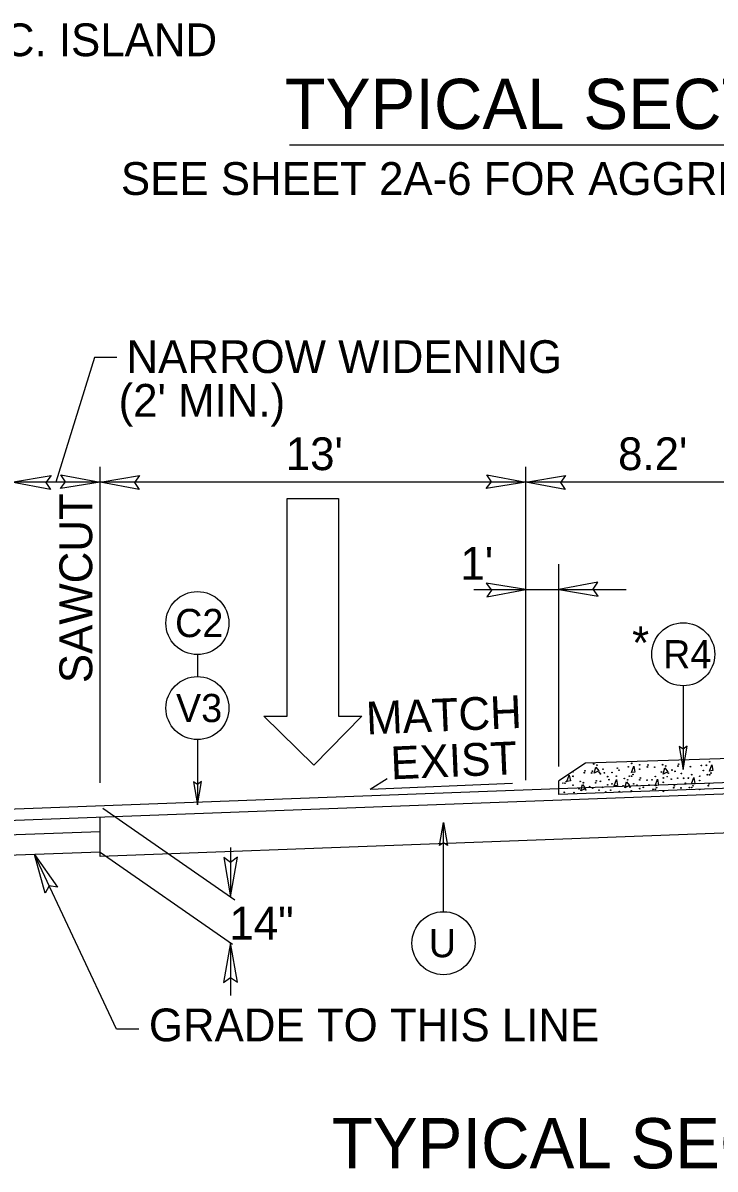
# Model space of a CAD drawing. Extents: x 573748 to 574632, y -54663 to -53209.
# Drawn here: x 574059.1 to 574090.8, y -53553.4 to -53500.9 of the extents above; entities that cross this region are included whole.
import ezdxf

# ---------------------------------------------------------------- set-up
doc = ezdxf.new("R2010")
doc.units = 0
for name, color, linetype in [('Prop Dimension', 7, 'Continuous'), ('Prop Dimension Text', 7, 'Continuous'), ('Prop Lane Arrow CELL', 7, 'Continuous'), ('Prop Terminator CELL', 7, 'Continuous'), ('Typical Arrow Superelevation CELL', 7, 'Continuous'), ('Typical Curb CELL', 7, 'Continuous'), ('Typical ID Circle CELL', 7, 'Continuous'), ('Typical Pavement Slope CELL', 7, 'Continuous'), ('Typical Terminator CELL', 7, 'Continuous'), ('Typical Text General CELL', 7, 'Continuous'), ('Typical Text ID Circle CELL', 7, 'Continuous'), ('Typical Text Label CELL', 7, 'Continuous')]:
    doc.layers.add(name, color=color, linetype=linetype)

msp = doc.modelspace()

# ---------------------------------------------------------------- linework, layer by layer
at = {"layer": 'Prop Dimension'}
for p, q in [((574062.619, -53535.664), (574062.619, -53521.214)), ((574082.119, -53535.548), (574082.119, -53521.214)), ((574062.619, -53521.907), (574058.56, -53521.907)), ((574082.119, -53521.907), (574062.619, -53521.907)), ((574094.001, -53521.907), (574082.119, -53521.907)), ((574083.619, -53534.926), (574083.619, -53525.657)), ((574079.741, -53526.824), (574086.705, -53526.824)), ((574084.854, -53534.767), (574083.619, -53535.575)), ((574094.001, -53534.479), (574084.854, -53534.767)), ((574094.001, -53535.561), (574083.619, -53535.949)), ((574083.619, -53536.206), (574083.619, -53535.575)), ((574094.001, -53535.818), (574083.619, -53536.206)), ((574062.752, -53536.827), (574068.787, -53541.022)), ((574094.001, -53537.874), (574062.619, -53539.048)), ((574062.619, -53538.84), (574068.684, -53543.056)), ((574062.619, -53539.048), (574062.619, -53538.84)), ((574068.598, -53538.637), (574068.598, -53540.89)), ((574068.598, -53542.996), (574068.598, -53545.398))]:
    msp.add_line(p, q, dxfattribs=at)
for points in [[(574063.388, -53516.206), (574062.367, -53516.206), (574060.59, -53521.907)], [(574064.398, -53546.943), (574063.377, -53546.943), (574059.618, -53538.952)]]:
    msp.add_lwpolyline(points, dxfattribs=at)
at = {"layer": 'Prop Lane Arrow CELL'}
for p, q in [((574071.193, -53532.624), (574071.193, -53522.649)), ((574071.193, -53522.649), (574073.545, -53522.649)), ((574073.545, -53522.649), (574073.545, -53532.624)), ((574072.405, -53534.869), (574070.125, -53532.624)), ((574070.125, -53532.624), (574071.193, -53532.624)), ((574074.613, -53532.624), (574072.405, -53534.869)), ((574073.545, -53532.624), (574074.613, -53532.624))]:
    msp.add_line(p, q, dxfattribs=at)
at = {"layer": 'Prop Terminator CELL'}
for points in [[(574060.357, -53522.24), (574058.56, -53521.907), (574060.375, -53521.61), (574060.141, -53521.927)], [(574060.822, -53521.574), (574062.619, -53521.907), (574060.804, -53522.204), (574061.039, -53521.886)], [(574064.415, -53522.24), (574062.619, -53521.907), (574064.433, -53521.61), (574064.199, -53521.927)], [(574080.322, -53521.574), (574082.119, -53521.907), (574080.304, -53522.204), (574080.539, -53521.886)], [(574083.915, -53522.24), (574082.119, -53521.907), (574083.933, -53521.61), (574083.699, -53521.927)], [(574080.322, -53527.158), (574082.119, -53526.824), (574080.304, -53526.528), (574080.539, -53526.845)], [(574085.415, -53526.491), (574083.619, -53526.824), (574085.433, -53527.121), (574085.199, -53526.804)], [(574060.104, -53540.714), (574059.618, -53538.952), (574060.678, -53540.454), (574060.291, -53540.383)], [(574068.288, -53539.09), (574068.598, -53540.89), (574068.918, -53539.08), (574068.598, -53539.31)], [(574068.908, -53544.796), (574068.598, -53542.996), (574068.278, -53544.806), (574068.598, -53544.576)]]:
    msp.add_lwpolyline(points, close=True, dxfattribs=at)
at = {"layer": 'Typical Arrow Superelevation CELL'}
for q in [(574075.763, -53535.47), (574081.509, -53535.682)]:
    msp.add_line((574074.991, -53535.961), q, dxfattribs=at)
at = {"layer": 'Typical Curb CELL'}
for p, q in [((574085.248, -53535.231), (574085.325, -53534.952)), ((574085.325, -53534.952), (574085.459, -53535.125)), ((574086.947, -53535.202), (574087.054, -53534.909)), ((574087.054, -53534.909), (574087.101, -53535.179)), ((574090.519, -53535.135), (574090.626, -53534.842)), ((574090.626, -53534.842), (574090.673, -53535.112)), ((574083.999, -53535.608), (574084.106, -53535.315)), ((574084.106, -53535.315), (574084.153, -53535.585)), ((574085.459, -53535.125), (574085.248, -53535.231)), ((574087.101, -53535.179), (574086.947, -53535.202)), ((574088.401, -53535.268), (574088.478, -53534.989)), ((574088.612, -53535.162), (574088.401, -53535.268)), ((574088.478, -53534.989), (574088.612, -53535.162)), ((574089.697, -53535.718), (574089.805, -53535.425)), ((574089.805, -53535.425), (574089.852, -53535.696)), ((574090.673, -53535.112), (574090.519, -53535.135)), ((574084.153, -53535.585), (574083.999, -53535.608)), ((574084.629, -53536.033), (574084.706, -53535.754)), ((574084.84, -53535.927), (574084.629, -53536.033)), ((574084.706, -53535.754), (574084.84, -53535.927)), ((574086.153, -53535.815), (574086.26, -53535.522)), ((574086.307, -53535.792), (574086.153, -53535.815)), ((574086.26, -53535.522), (574086.307, -53535.792)), ((574086.652, -53535.902), (574086.729, -53535.623)), ((574086.863, -53535.796), (574086.652, -53535.902)), ((574086.729, -53535.623), (574086.863, -53535.796)), ((574088.031, -53535.803), (574088.139, -53535.51)), ((574088.186, -53535.78), (574088.031, -53535.803)), ((574088.139, -53535.51), (574088.186, -53535.78)), ((574089.852, -53535.696), (574089.697, -53535.718))]:
    msp.add_line(p, q, dxfattribs=at)
for centre in [(574085.222, -53534.805), (574085.368, -53534.864), (574086.81, -53534.935), (574086.963, -53534.78), (574087.33, -53534.846), (574087.681, -53534.943), (574087.709, -53534.855), (574088.018, -53534.953), (574088.375, -53534.842), (574088.522, -53534.9), (574089.081, -53534.903), (574089.109, -53534.816), (574089.316, -53534.92), (574089.344, -53534.832), (574089.653, -53534.93), (574090.156, -53534.879), (574090.382, -53534.868), (574090.535, -53534.713), (574084.274, -53535.37), (574084.282, -53535.167), (574084.791, -53535.209), (574084.82, -53535.121), (574085.129, -53535.218), (574085.165, -53535.139), (574085.479, -53535.193), (574085.531, -53535.254), (574085.651, -53535.048), (574085.715, -53535.212), (574085.858, -53535.386), (574086.056, -53535.195), (574086.258, -53535.366), (574086.307, -53534.996), (574086.376, -53535.094), (574086.626, -53535.476), (574086.857, -53535.367), (574086.954, -53535.367), (574087.017, -53535.291), (574087.323, -53535.048), (574087.36, -53535.45), (574088.048, -53535.381), (574088.319, -53535.175), (574088.415, -53535.446), (574088.633, -53535.229), (574088.804, -53535.085), (574088.951, -53535.144), (574089.062, -53535.458), (574089.241, -53535.24), (574089.335, -53535.463), (574089.56, -53535.452), (574089.714, -53535.297), (574090.081, -53535.362), (574090.237, -53535.104), (574090.429, -53535.3), (574090.526, -53535.3), (574090.589, -53535.223), (574083.809, -53535.689), (574083.905, -53535.689), (574083.969, -53535.612), (574084.279, -53535.779), (574084.547, -53535.94), (574084.603, -53535.607), (574084.75, -53535.665), (574084.861, -53535.994), (574085.032, -53535.85), (574085.179, -53535.909), (574085.309, -53535.668), (574085.337, -53535.581), (574085.469, -53536.005), (574085.527, -53535.601), (574085.619, -53535.874), (574085.862, -53535.764), (574085.919, -53535.525), (574086.003, -53536.007), (574086.055, -53535.713), (574086.57, -53535.81), (574086.773, -53535.535), (574086.884, -53535.864), (574087.055, -53535.719), (574087.202, -53535.778), (574087.332, -53535.537), (574087.333, -53535.936), (574087.492, -53535.874), (574087.669, -53535.547), (574087.75, -53535.772), (574087.895, -53535.536), (574087.942, -53535.968), (574088.039, -53535.968), (574088.102, -53535.892), (574088.408, -53535.649), (574088.771, -53535.505), (574088.886, -53535.895), (574088.914, -53535.808), (574089.224, -53535.905), (574089.416, -53535.688), (574089.608, -53535.884), (574089.704, -53535.884), (574089.768, -53535.807), (574090.073, -53535.565), (574090.078, -53535.975), (574090.467, -53535.803), (574090.496, -53535.716), (574083.875, -53536.105), (574084.319, -53536.114), (574085.775, -53536.093), (574086.392, -53536.064), (574086.948, -53536.042), (574088.412, -53536.059)]:
    msp.add_ellipse(centre, major_axis=(0.0001, 0.0192), ratio=0.533333, dxfattribs=at)
msp.add_ellipse((574088.585, -53535.41), major_axis=(-0.0001, -0.0219), ratio=0.533333, start_param=2.050606, end_param=4.270718, dxfattribs=at)
at = {"layer": 'Typical ID Circle CELL'}
for p, q in [((574067.078, -53529.801), (574067.078, -53530.806)), ((574089.322, -53531.23), (574089.322, -53535.056)), ((574067.078, -53533.691), (574067.078, -53536.677)), ((574078.345, -53541.569), (574078.345, -53537.486))]:
    msp.add_line(p, q, dxfattribs=at)
for centre in [(574067.078, -53528.358), (574089.322, -53529.787), (574067.078, -53532.248), (574078.345, -53543.012)]:
    msp.add_circle(centre, 1.443, dxfattribs=at)
at = {"layer": 'Typical Pavement Slope CELL'}
for p, q in [((574083.619, -53535.949), (574052.56, -53537.111)), ((574094.001, -53536.075), (574052.064, -53537.644)), ((574062.619, -53538.84), (574062.619, -53537.249)), ((574062.619, -53537.909), (574051.426, -53538.328)), ((574062.619, -53538.84), (574050.528, -53539.292))]:
    msp.add_line(p, q, dxfattribs=at)
at = {"layer": 'Typical Terminator CELL'}
for points in [[(574089.14, -53534.002), (574089.322, -53535.056), (574089.509, -53533.996), (574089.322, -53534.131)], [(574066.896, -53535.623), (574067.078, -53536.677), (574067.265, -53535.617), (574067.078, -53535.752)], [(574078.163, -53538.541), (574078.345, -53537.486), (574078.532, -53538.546), (574078.345, -53538.412)]]:
    msp.add_lwpolyline(points, close=True, dxfattribs=at)
at = {"layer": 'Typical Text Label CELL'}
msp.add_line((574071.293, -53506.466), (574107.5, -53506.466), dxfattribs=at)

# ---------------------------------------------------------------- texts
at = {"layer": 'Prop Dimension'}
msp.add_text('GRADE TO THIS LINE', height=1.5, rotation=360, dxfattribs=at).set_placement((574064.857, -53547.502))
at = {"layer": 'Prop Dimension Text'}
for s, height, p in [('TYPICAL SECTION NO. 2', 2.3, (574071.073, -53505.746)), ('NARROW WIDENING', 1.5, (574063.829, -53516.913)), ("(2' MIN.)", 1.5, (574063.47, -53518.913)), ("13'", 1.5, (574071.124, -53521.357)), ("8.2'", 1.5, (574086.339, -53521.357)), ("1'", 1.5, (574079.121, -53526.374)), ('*', 1.5, (574086.981, -53530.008)), ('14"', 1.5, (574068.544, -53542.846)), ('TYPICAL SECTION NO. 3', 2.3, (574073.229, -53553.318))]:
    msp.add_text(s, height=height, dxfattribs=at).set_placement(p)
for s, rotation, p in [('SAWCUT', 90, (574062.262, -53531.108)), ('MATCH', 2.4521, (574074.83, -53533.461)), ('EXIST', 2.4521, (574075.953, -53535.515))]:
    msp.add_text(s, height=1.5, rotation=rotation, dxfattribs=at).set_placement(p)
at = {"layer": 'Typical Text General CELL'}
for s, p in [('SEE PLANS FOR LIMITS OF CONC. ISLAND', (574026.853, -53502.41)), ('SEE SHEET 2A-6 FOR AGGREGATE SUBGRADE DETAIL', (574063.577, -53508.76))]:
    msp.add_text(s, height=1.5, dxfattribs=at).set_placement(p)
at = {"layer": 'Typical Text ID Circle CELL'}
for s, height, p in [('C2', 1.2912, (574066.057, -53529.001)), ('R4', 1.2912, (574088.399, -53530.43)), ('V3', 1.2912, (574066.099, -53532.891)), ('U', 1.291, (574077.674, -53543.655))]:
    msp.add_text(s, height=height, dxfattribs=at).set_placement(p)

doc.saveas('drawing.dxf')
